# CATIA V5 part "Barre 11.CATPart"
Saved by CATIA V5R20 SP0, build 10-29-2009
Part number: Barre 11
Bounding box of the stored display mesh (mm): x -169.738 to 169.738, y -68.134 to 68.134, z 10 to 20
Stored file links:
  C:\Users\Matthieu\Desktop\IFMA\Cours 2A\Thinkmotion\Projet_IAO_714_Matthieu_Perrusset\Barre 11.CATPart
  C:\Users\Matthieu\Desktop\IFMA\Cours 2A\Thinkmotion\Ass_skl_IAO.CATProduct
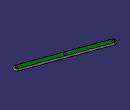
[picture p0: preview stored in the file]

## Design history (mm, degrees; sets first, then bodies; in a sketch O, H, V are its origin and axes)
AxisSystem1: origin (0, 0, 0), X (1, 0, 0), Y (0, 1, 0), Z (0, 0, 1)
Set1
  Plane1 "Plan_Ref": linked copy from another document
  Line1 "Barre_111": linked copy from another document
  Line2 "Axe_Pivot_b11b10": linked copy from another document
  Line3 "Axe_Pivot_b11b2": linked copy from another document
  Line4 "Barre_112": linked copy from another document
Body1 (main body)
  Sketch1 on Plane1, origin (0, 0, 0), H (1, 0, 0), V (0, 1, 0)
    line L1 (156.3275, -67.5404) -> (-163.1679, 48.7465)
    arc A1 centre (-159.7477, 58.1434) radius 10 from (-163.1679, 48.7465) to (-156.3275, 67.5404) cw
    point P3 (-159.7477, 58.1434)
    line L2 (-156.3275, 67.5404) -> (163.1679, -48.7465)
    arc A2 centre (159.7477, -58.1434) radius 10 from (163.1679, -48.7465) to (156.3275, -67.5404) cw
    point P6 (159.7477, -58.1434)
    reference projected line E1 (159.7477, -58.1434) -> (0, 0) from Line1
    reference projected line E2 (159.7477, -58.1434) -> (0, 0) from Line1
    reference projected point E3 (159.7477, -58.1434) from Line2
    reference projected point E4 (-159.7477, 58.1434) from Line3
    reference projected line E5 (0, 0) -> (-159.7477, 58.1434) from Line4
    reference projected line E6 (0, 0) -> (-159.7477, 58.1434) from Line4
    circle A3 centre (159.7477, -58.1434) radius 5
    circle A4 centre (0, 0) radius 5
    circle A5 centre (-159.7477, 58.1434) radius 5
    distance E5 L1 = 10
    distance E6 L2 = 10
    distance P6 A2 = 10
    distance P3 A1 = 10
    radius A3 = 5
    radius A4 = 5
    radius A5 = 5
    parallelism: E1 L2, E2 L1
    coincidence: P6 E3, P3 E4
  Pad1: profile Sketch1, direction (0, 0, 1), length 20, opposite side length -10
